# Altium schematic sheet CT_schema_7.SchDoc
size 147 x 119 mm
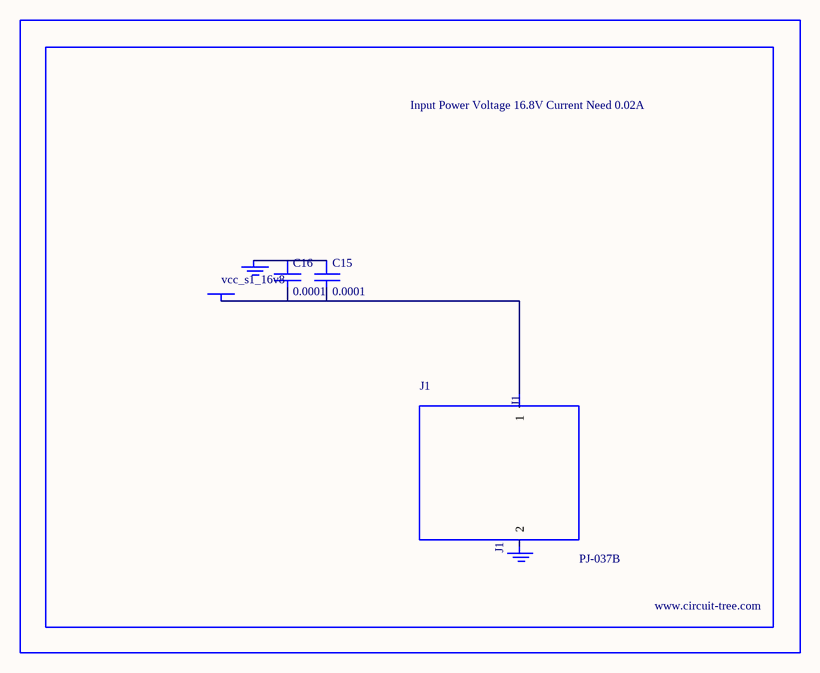
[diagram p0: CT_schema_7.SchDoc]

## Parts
BORDER6  (no value)
C15  0.0001  [EXV-9H]
C16  0.0001  [EXV-9H]
GND_INSTANCE_6_0  (no value)
GND_INSTANCE_6_1  (no value)
J1  PJ-037B  [PJ-037B_PACKAGE]
POWER_INSTANCE_6_0  vcc_s1_16v8

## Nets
NetC15_1: C15.1 C16.1 GND_INSTANCE_6_0.0(GND)
NetC15_2: C15.2 C16.2 J1.1 POWER_INSTANCE_6_0.0(PWR)

Not connected (* = marked no-connect by the designer): GND_INSTANCE_6_1 0(GND); J1 2

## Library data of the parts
BORDER6 = BORDER_PAGE6
C15 C16 = EDK107M035A9HAA
GND_INSTANCE_6_0 GND_INSTANCE_6_1 = GND
POWER_INSTANCE_6_0 = PWR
